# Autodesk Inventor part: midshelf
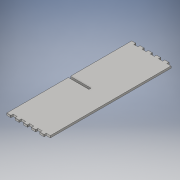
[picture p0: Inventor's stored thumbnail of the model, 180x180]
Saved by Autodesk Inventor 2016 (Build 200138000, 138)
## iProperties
Created: 2017-03
Part Number: midshelf
Material: Generic
Document SubType Name: Modeling
Designer: Corey
Density: 1 g/cm^3
Appearance: Default
Author: Corey
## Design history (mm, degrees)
sketch "Sketch1"
  geometry: L1 (0, 0)-(368.3, 0); L2 (368.3, 0)-(368.3, -1117.6); L3 (368.3, -1117.6)-(0, -1117.6); L4 (0, -1117.6)-(0, 0)
  constraints: 8 end point, 2 parallel, 1 horizontal, 1 perpendicular
  dimensions: "d0" = 368.3 distance of L2.end L3.end (= panel); "d1" = 1117.6 distance of L1.end L2.end (= width)
extrude "body" new body sketch "Sketch1" distance "d2" = 18.034 (= thick); taper "d3" = 0 deg
sketch "Sketch2"
  geometry: L1 (-368.3, 0)-(0, 0) reference; L2 (0, 0)-(-36.83, 0); L3 (-36.83, 0)-(-36.83, 21.209); L4 (-36.83, 21.209)-(0, 21.209); L5 (0, 21.209)-(0, 0); L6 (0, 0)-(0, 1117.6) reference; L7 (0, 558.8)-(-368.3, 558.8); L8 (-368.3, 1117.6)-(-368.3, 0) reference; L9 (0, 1117.6)-(-36.83, 1117.6); L10 (-36.83, 1117.6)-(-36.83, 1096.391); L11 (-36.83, 1096.391)-(0, 1096.391); L12 (0, 1096.391)-(0, 1117.6)
  constraints: 18 end point, 3 symmetric about line, 2 midpoint, 2 parallel, 1 horizontal, 1 perpendicular
  dimensions: "d4" = 36.83 distance of L3.end L4.end (= 0.1 x panel); "d5" = 21.209 distance of L2.end L3.end (= thick + 0.5 x bit)
extrude "sidetab" cut sketch "Sketch2" stored distance "d6" = 18.034 (= thick); taper "d7" = 0 deg
pattern_linear "sidetabP" dims "d10" = 73.66 (= 0.2 x panel)
chamfer "type2pressfit" distance "d11" = 2.25425 (= 0.125 x thick); stored, may be unused: second distance "d12" = 3.175, angle "d13" = 45 deg
sketch "Sketch4"
  geometry: L1 (-184.15, 549.783)-(-368.3, 549.783); L2 (-368.3, 549.783)-(-368.3, 567.817); L3 (-368.3, 567.817)-(-184.15, 567.817); L4 (-184.15, 567.817)-(-184.15, 549.783); L5 (-184.15, 549.783)-(-368.3, 567.817); L6 (-368.3, 549.783)-(-184.15, 567.817); L7 (0, 21.209)-(0, 1096.391) reference; L8 (-145.066, 0)-(-112.744, 0) reference; L9 (-368.3, 1115.346)-(-368.3, 2.254) reference; 2 further points
  constraints: 12 end point, 2 midpoint, 2 parallel, 1 collinear, 1 perpendicular
  dimensions: "d25" = 184.15 distance of L2.end L3.end (= 0.5 x panel); "d26" = 18.034 distance of L1.end L2.end (= thick); "d27" = 558.8 distance from line of L8 point (-276.225, 558.8) (= 0.5 x width)
extrude "midslot" cut sketch "Sketch4" stored distance "d28" = 25.4; taper "d29" = 0 deg
chamfer "type2pressfit2" distance "d30" = 3.175; stored, may be unused: second distance "d31" = 3.175, angle "d32" = 45 deg
body "Solid1"
other parameters: "height" = 1917.7 [user parameter], "width" = 1117.6 [user parameter; used in 2 equation terms], "depth" = 425.45 [user parameter], "thick" = 18.034 [user parameter; used in 5 equation terms], "bit" = 6.35 [user parameter; used in 1 equation term], "top" = 152.4 [user parameter], "panel" = 368.3 [user parameter; used in 4 equation terms], "sweater" = 330.2 [user parameter], "shoe" = 152.4 [user parameter], "osb" = 19.05 [user parameter]
